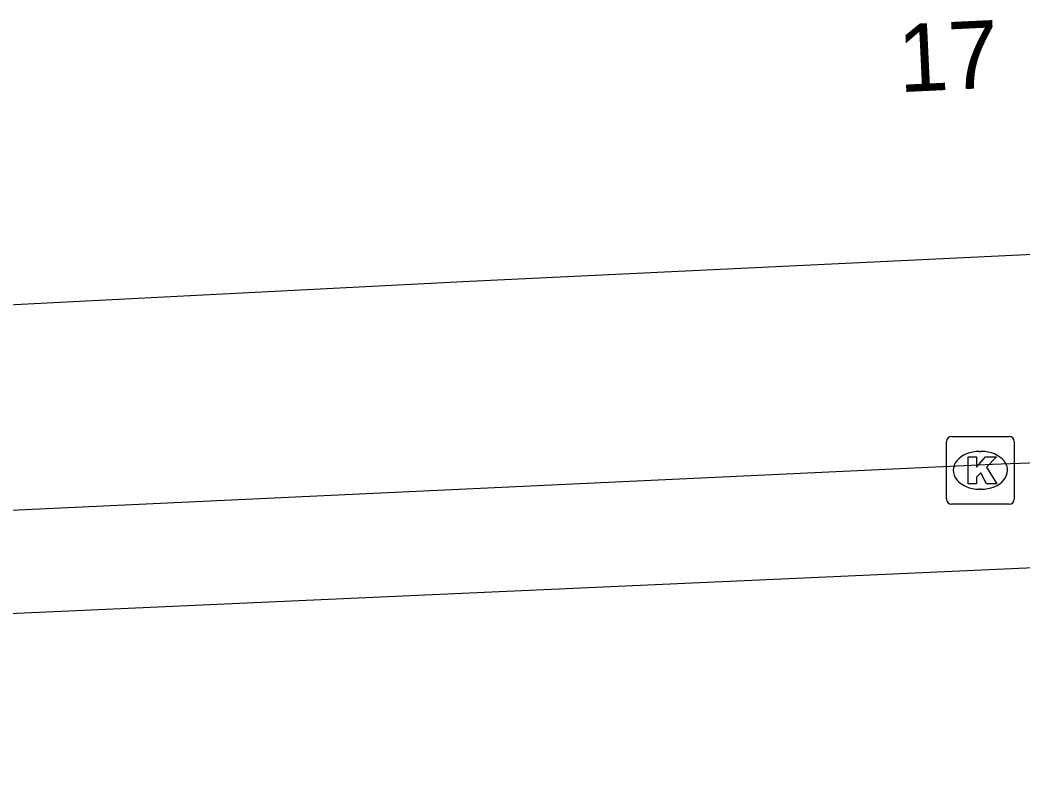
# Model space of a CAD drawing. Extents: x 161087 to 161922, y 382574 to 383873.
# Drawn here: x 161840.07 to 161854.89, y 382844.03 to 382855.24 of the extents above; entities that cross this region are included whole.
import ezdxf

# ---------------------------------------------------------------- set-up
doc = ezdxf.new("R2010")
doc.units = 0
for name, color, linetype in [('IMGEO_Kolk', 7, 'Continuous'), ('IMGEO_Pand', 7, 'Continuous'), ('IMGEO_Pand_nummerreeks', 7, 'Continuous'), ('IMGEO_Rijbaan_lokaal_gesloten', 7, 'Continuous')]:
    doc.layers.add(name, color=color, linetype=linetype)

msp = doc.modelspace()

# ---------------------------------------------------------------- linework, layer by layer
at = {"layer": 'IMGEO_Kolk'}
for p, q in [((161853.761, 382848.166), (161853.761, 382849.018)), ((161853.836, 382849.092), (161854.688, 382849.092)), ((161854.762, 382849.018), (161854.762, 382848.166)), ((161854.249, 382848.872), (161854.274, 382848.872)), ((161854.272, 382848.312), (161854.247, 382848.312)), ((161854.688, 382848.092), (161853.836, 382848.092))]:
    msp.add_line(p, q, dxfattribs=at)
for points in [[(161853.761, 382848.166), (161853.761, 382849.018)], [(161853.836, 382849.092), (161854.688, 382849.092)], [(161854.762, 382849.018), (161854.762, 382848.166)], [(161854.082, 382848.792), (161854.205, 382848.792), (161854.205, 382848.641), (161854.335, 382848.792), (161854.499, 382848.792), (161854.353, 382848.641), (161854.506, 382848.392), (161854.354, 382848.392), (161854.269, 382848.556), (161854.205, 382848.489), (161854.205, 382848.392), (161854.082, 382848.392), (161854.082, 382848.792)], [(161854.688, 382848.092), (161853.836, 382848.092)]]:
    msp.add_lwpolyline(points, dxfattribs=at)
for centre, start, end in [((161853.838, 382849.016), 91.552, 178.448), ((161853.838, 382849.016), 91.552, 178.448), ((161854.686, 382849.016), 1.552, 88.448), ((161854.686, 382849.016), 1.552, 88.448), ((161853.838, 382848.168), 181.552, 268.448), ((161853.838, 382848.168), 181.552, 268.448), ((161854.686, 382848.168), 271.552, 358.448), ((161854.686, 382848.168), 271.552, 358.448)]:
    msp.add_arc(centre, 0.0765, start, end, dxfattribs=at)
for centre, major_axis, ratio, start_param, end_param in [((161854.248, 382848.592), (-0.387, 0.002), 0.722429, 4.712389, 7.853982), ((161854.273, 382848.592), (-0.39, 0.002), 0.717154, 1.570796, 4.712389)]:
    msp.add_ellipse(centre, major_axis=major_axis, ratio=ratio, start_param=start_param, end_param=end_param, dxfattribs=at)
at = {"layer": 'IMGEO_Pand'}
msp.add_lwpolyline([(161833.32, 382850.708), (161835.282, 382850.802), (161846.429, 382851.37), (161846.616, 382851.379), (161861.213, 382852.08), (161861.326, 382851.991), (161861.448, 382851.971), (161861.574, 382851.99)], dxfattribs=at)
at = {"layer": 'IMGEO_Rijbaan_lokaal_gesloten'}
for points in [[(161832.263, 382847.644), (161854.439, 382848.685), (161862.869, 382848.994)], [(161855.93, 382847.19), (161807.883, 382845.036), (161787.742, 382844.105), (161786.091, 382844.033)]]:
    msp.add_lwpolyline(points, dxfattribs=at)

# ---------------------------------------------------------------- texts
at = {"layer": 'IMGEO_Pand_nummerreeks'}
msp.add_text('17', height=1, rotation=2.7445, dxfattribs=at).set_placement((161853.066, 382854.177))

doc.saveas('drawing.dxf')
